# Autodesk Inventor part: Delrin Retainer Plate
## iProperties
Shininess: 64.0
Length Units: 11272
Angle Units: 11279
Time Units: 11290
Mass Units: 11286
Length Display Precision: 3
Angle Display Precision: 2
Compacted: True
Part Number: Delrin Retainer Plate
Document SubType Name: Modeling
Created: 2003-10
Designer: jpittman
Manufacturer: Standard
Standards Organization: Custom
Density: 0.0
Volumn: 0.0
Area: 0.0
PropertySet Name: Model Information
Control State: 0
Master: False
Checked Out: False
Author: jpittman
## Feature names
1. Extrusion1
2. Extrusion2
3. Extrusion3
4. Hole1
5. Hole2
6. Hole3
